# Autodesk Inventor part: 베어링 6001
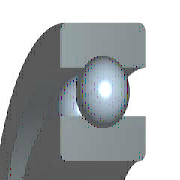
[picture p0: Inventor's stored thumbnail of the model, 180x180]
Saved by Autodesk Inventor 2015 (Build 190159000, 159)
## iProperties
IsCustomPart: 0
Created: 2015-10
Part Number: 베어링 6001
Material: 강철, 연강
Description: 깊은 그루브 볼 베어링
Document SubType Name: Modeling
Standard: KS B 2023
Designer: mdu
Standards Organization: KS
Language: ko-KR
Size Designation: 6001 - 12 x 28 x 8
Categories: <MemberInstance><Categories><Category DisplayName="샤프트 부품" InternalName="7f7aeb1f-a693-4053-b835-cee3144e0d98" Mnemonic="SHFT"><Category DisplayName="베어링" Inter
Density: 7.86 g/cm^3
Mass: 21.4854 g
Surface Area: 31.1809 cm^2
Volume: 2.73351 cm^3
Appearance: 강철
Author: mdu
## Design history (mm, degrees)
sketch "스케치" dims "d0" = 4.16 (= -0.26 x WD + 0.26 x BD)
  geometry: L1 (1.92, 10)-(6.08, 10); L2 (4, 10)-(4, 7.92); L3 (4, 10)-(4, 12.08); L4 (2.454, 8.608)-(0, 8.608); L5 (0, 6)-(8, 6); L6 (2.454, 11.392)-(0, 11.392); L7 (0, 14)-(8, 14); L8 (8, 6)-(8, 8.608); L9 (5.546, 8.608)-(8, 8.608); L10 (5.546, 11.392)-(8, 11.392); L11 (8, 14)-(8, 11.392); L12 (-1.4, 0)-(8.4, 0) reference; L13 (0, -0.3)-(0, 5.3) reference
  constraints: 22 end point, 4 point on line, 2 collinear, 2 perpendicular, 2 symmetric about line, 1 midpoint, 1 parallel, 14 other
  dimensions: "d9" = 12 diameter of L5 L12 (= WD); "d11" = 28 diameter of L7 L12 (= BD); "d12" = 8 distance between parallel lines of L8 L13 (= KB); "d13" = 17.216 diameter of L9 L12 (= 0.326 x BD + 0.674 x WD)
revolve "본체" stored, may be unused: angle "d6" = 90 deg
revolve "볼" stored, may be unused: angle "d7" = 90 deg
pattern_circular "IDS_ARRAYBALL[SIMPL:T]" dims angle "d3" = 360 deg
body "Solid1"
fillet "모깎기1" dims "d1" = 0.3 (= KRS)
other parameters: "WD" = 12 [user parameter; used in 5 equation terms], "BD" = 28 [user parameter; used in 5 equation terms], "KB" = 8 [user parameter; used in 1 equation term], "KRS" = 0.3 [user parameter; used in 1 equation term], "d4" = 0, "d5" = 0, "d8" = 0, "d14" = 0, "d15" = 0, "BBA" = 0 [user parameter], "BC0" = 2360000 [user parameter], "BC" = 5070000 [user parameter], "BR" = 14 (= 0.5 x BD) [user parameter], "WR" = 6 (= 0.5 x WD) [user parameter]
